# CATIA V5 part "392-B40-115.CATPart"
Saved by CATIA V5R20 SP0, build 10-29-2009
Part number: 392-B40-115
Definition: NONE
Nomenclature: 392-B40-115
Source: Unknown
Description: 392-B40-115
Bounding box of the stored display mesh (mm): x 0 to 115, y -18.893 to 18.893, z -18.75 to 18.559
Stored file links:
  C:\Users\Utente\Desktop\IO LAVORO\3D X SITO CF\X SITO\3D files 392B\392-B40-115.CATPart
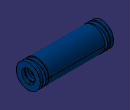
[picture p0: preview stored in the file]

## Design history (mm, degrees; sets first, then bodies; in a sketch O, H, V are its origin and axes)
Body1 "392-B40-115" (main body)
  Solid1: solid without history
